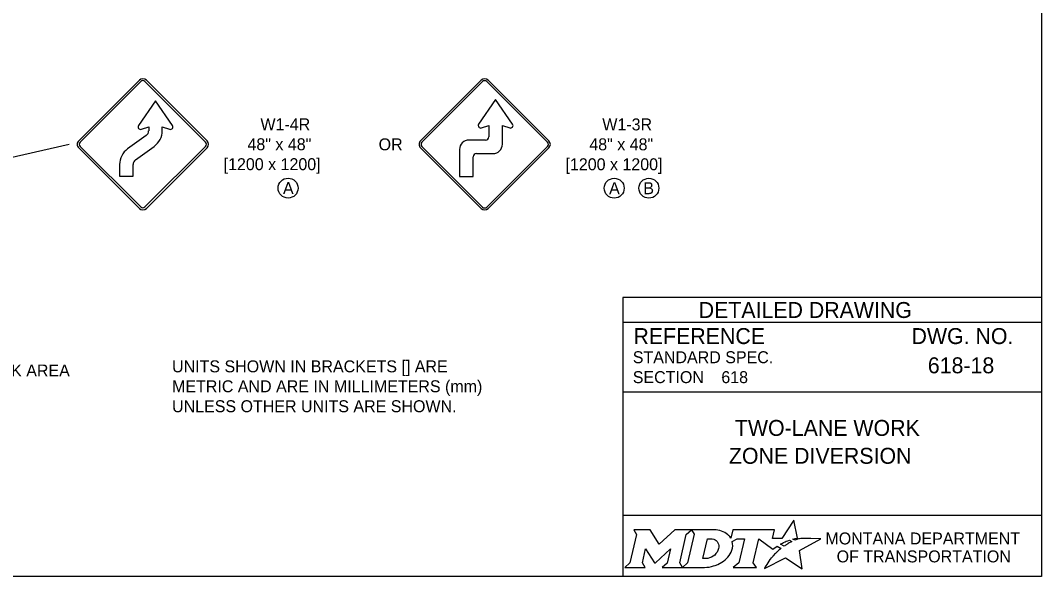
# Model space of a CAD drawing. Extents: x 49991.4 to 50021, y 49987.6 to 50011.4.
# Drawn here: x 50011.63 to 50016.75, y 49987.8 to 49990.59 of the extents above; entities that cross this region are included whole.
import ezdxf

# ---------------------------------------------------------------- set-up
doc = ezdxf.new("R2010")
doc.units = 0
for name, color, linetype in [('Default', 7, 'Continuous'), ('Level 1', 7, 'Continuous'), ('Level 2', 7, 'Continuous'), ('Level 3', 7, 'Continuous'), ('Level 5', 7, 'Continuous')]:
    doc.layers.add(name, color=color, linetype=linetype)

msp = doc.modelspace()

# ---------------------------------------------------------------- linework, layer by layer
at = {"layer": 'Default'}
for points in [[(50015.5126, 49987.9811), (50015.5023, 49987.9867), (50015.5139, 49987.9895), (50015.5255, 49987.9915), (50015.5081, 49988.0816), (50015.4486, 49987.9903), (50015.4013, 49987.9896), (50015.4116, 49988.0337), (50015.2024, 49988.0338), (50015.1923, 49987.9913), (50015.1865, 49987.9996)], [(50014.7056, 49988.0338), (50014.7197, 49988.0104), (50014.6862, 49987.8671), (50014.6605, 49987.8446), (50014.7621, 49987.8446), (50014.7486, 49987.8674), (50014.7648, 49987.9375), (50014.8085, 49987.8685), (50014.8138, 49987.8685), (50014.8889, 49987.938), (50014.8725, 49987.8669), (50014.8478, 49987.8449), (50014.9494, 49987.8449), (50014.9356, 49987.8682), (50014.9688, 49988.0106)], [(50014.9688, 49988.0106), (50014.9941, 49988.0338), (50014.9117, 49988.0338), (50014.8321, 49987.9608), (50014.7876, 49988.0335), (50014.7056, 49988.0338)], [(50015.1077, 49988.0338), (50014.9941, 49988.0338), (50015.0088, 49988.0109), (50014.9749, 49987.8671), (50014.9494, 49987.8449), (50015.06, 49987.8449)], [(50015.1317, 49987.9471), (50015.1305, 49987.939), (50015.1273, 49987.9297), (50015.1231, 49987.9215), (50015.1175, 49987.914), (50015.111, 49987.9071), (50015.1031, 49987.9008), (50015.0948, 49987.8961), (50015.0857, 49987.8922), (50015.0766, 49987.8899), (50015.0674, 49987.889), (50015.0515, 49987.889), (50015.0751, 49987.989), (50015.0911, 49987.989), (50015.0987, 49987.9884), (50015.1063, 49987.9865), (50015.1129, 49987.9835), (50015.119, 49987.9793), (50015.1238, 49987.9743), (50015.1275, 49987.9683), (50015.1302, 49987.9621), (50015.1318, 49987.9547), (50015.1318, 49987.9517), (50015.1317, 49987.9471)], [(50015.1991, 49987.9747), (50015.2237, 49987.9878), (50015.2606, 49987.9878), (50015.232, 49987.8673), (50015.2045, 49987.8446), (50015.3207, 49987.8446), (50015.3037, 49987.8675), (50015.3319, 49987.9877), (50015.4032, 49987.936), (50015.4243, 49987.9511), (50015.444, 49987.9402)], [(50015.3882, 49987.8843), (50015.3729, 49987.8599), (50015.3682, 49987.8524), (50015.3624, 49987.8438), (50015.3601, 49987.8395), (50015.4654, 49987.8926), (50015.5493, 49987.8375), (50015.5362, 49987.9302), (50015.6431, 49987.9886), (50015.5938, 49987.9894), (50015.5637, 49987.9898), (50015.5429, 49987.9901), (50015.5361, 49987.9886), (50015.5312, 49987.9874), (50015.5228, 49987.9851), (50015.5126, 49987.9811)], [(50015.4622, 49987.9535), (50015.4598, 49987.9518), (50015.4415, 49987.9614), (50015.4518, 49987.9671), (50015.4559, 49987.9693), (50015.4645, 49987.9733), (50015.4702, 49987.9759), (50015.4781, 49987.9789), (50015.4854, 49987.9816), (50015.4972, 49987.9742), (50015.4932, 49987.9721), (50015.4886, 49987.9696), (50015.4844, 49987.9674), (50015.4794, 49987.9645), (50015.4775, 49987.9634), (50015.4748, 49987.9618), (50015.4723, 49987.9604), (50015.47, 49987.9588), (50015.4674, 49987.957), (50015.4647, 49987.9552), (50015.4622, 49987.9535)], [(50015.1057, 49987.8522), (50015.1141, 49987.8548), (50015.1271, 49987.8602), (50015.1475, 49987.8712)], [(50015.4021, 49987.9004), (50015.4021, 49987.9004)]]:
    msp.add_lwpolyline(points, dxfattribs=at)
for centre, radius, start, end in [((50015.1308, 49987.9554), 0.0709, 339.5329, 15.8582), ((50015.0868, 49987.9727), 0.1183, 300.9103, 339.1383)]:
    msp.add_arc(centre, radius, start, end, dxfattribs=at)
for centre, major_axis, ratio, start_param, end_param in [((50015.1056, 49987.9864), (0.0834, -0.0037), 0.568097, 0.61298, 1.570796), ((50015.1612, 49987.9937), (0.0361, -0.0295), 0.469099, 1.225588, 1.570796), ((50015.4119, 49987.9106), (-0.0098, -0.0102), 0.016458, 3.141593, 6.279097), ((50015.4329, 49987.9305), (-0.0112, -0.0097), 0.021651, 3.157348, 6.283185), ((50015.0603, 49987.9932), (0, 0.1484), 0.987302, 3.139398, 3.456847), ((50015.3952, 49987.8923), (-0.00694, -0.00806), 0.008222, 0, 3.137361)]:
    msp.add_ellipse(centre, major_axis=major_axis, ratio=ratio, start_param=start_param, end_param=end_param, dxfattribs=at)
at = {"layer": 'Level 1'}
for p, q in [((50011.9223, 49989.9854), (50012.2264, 49990.2894)), ((50011.9294, 49989.9783), (50012.2334, 49990.2824)), ((50012.2546, 49990.2824), (50012.5587, 49989.9783)), ((50012.2617, 49990.2894), (50012.5658, 49989.9854)), ((50013.6363, 49989.985), (50013.9404, 49990.289)), ((50013.6434, 49989.9779), (50013.9474, 49990.282)), ((50013.9687, 49990.282), (50014.2727, 49989.9779)), ((50013.9757, 49990.289), (50014.2798, 49989.985)), ((50012.3071, 49990.1861), (50012.2221, 49990.0624)), ((50012.3923, 49990.0624), (50012.3071, 49990.1861)), ((50014.0128, 49990.193), (50013.9277, 49990.0693)), ((50014.0979, 49990.0693), (50014.0128, 49990.193)), ((50012.2367, 49990.0427), (50012.2732, 49990.0545)), ((50012.2732, 49990.0545), (50012.2732, 49990.0357)), ((50012.3411, 49990.0357), (50012.3411, 49990.0545)), ((50012.3411, 49990.0545), (50012.3776, 49990.0427)), ((50013.9424, 49990.0497), (50013.9788, 49990.0615)), ((50013.9788, 49990.0615), (50013.9788, 49990.005)), ((50014.0468, 49989.9678), (50014.0468, 49990.0615)), ((50014.0468, 49990.0615), (50014.0832, 49990.0497)), ((50012.2611, 49990.012), (50012.1675, 49989.9445)), ((50012.2264, 49989.646), (50011.9223, 49989.95)), ((50012.2334, 49989.653), (50011.9294, 49989.9571)), ((50012.2072, 49989.8893), (50012.3008, 49989.9569)), ((50012.5587, 49989.9571), (50012.2546, 49989.653)), ((50012.5658, 49989.95), (50012.2617, 49989.646)), ((50013.9474, 49989.6526), (50013.6434, 49989.9567)), ((50013.9627, 49989.9888), (50013.8789, 49989.9888)), ((50014.2727, 49989.9567), (50013.9687, 49989.6526)), ((50013.9404, 49989.6456), (50013.6363, 49989.9496)), ((50013.832, 49989.9419), (50013.832, 49989.806)), ((50013.8999, 49989.806), (50013.8999, 49989.9047)), ((50013.9161, 49989.9208), (50013.9999, 49989.9208)), ((50014.2798, 49989.9496), (50013.9757, 49989.6456)), ((50012.1272, 49989.8658), (50012.1272, 49989.8075)), ((50012.1951, 49989.8075), (50012.1951, 49989.8658)), ((50012.1272, 49989.8075), (50012.1951, 49989.8075)), ((50013.832, 49989.806), (50013.8999, 49989.806))]:
    msp.add_line(p, q, dxfattribs=at)
msp.add_lwpolyline([(49999.3835, 49998.9992), (50016.7501, 49998.9992), (50016.7501, 49987.7988), (49999.3835, 49987.7988)], close=True, dxfattribs=at)
for centre, radius, start, end in [((50012.244, 49990.2718), 0.025, 45, 135), ((50012.244, 49990.2718), 0.015, 45, 135), ((50013.958, 49990.2714), 0.025, 45, 135), ((50013.958, 49990.2714), 0.015, 45, 135), ((50012.2327, 49990.0551), 0.0129, 145.4806, 287.9582), ((50012.3815, 49990.0551), 0.0129, 252.0418, 34.5194), ((50013.9384, 49990.062), 0.0129, 145.4806, 287.9582), ((50014.0872, 49990.062), 0.0129, 252.0418, 34.5194), ((50012.244, 49990.0357), 0.0291, 305.7972, 0), ((50012.244, 49990.0357), 0.0971, 305.7972, 0), ((50013.9626, 49990.005), 0.0162, 270, 0), ((50011.9399, 49989.9678), 0.025, 134.9998, 225), ((50011.9399, 49989.9678), 0.015, 134.9998, 225), ((50012.5481, 49989.9678), 0.015, 315, 45), ((50012.5481, 49989.9678), 0.025, 315, 45), ((50013.654, 49989.9673), 0.025, 134.9998, 225), ((50013.654, 49989.9673), 0.015, 134.9998, 225), ((50013.8789, 49989.9419), 0.0469, 90, 180), ((50013.9998, 49989.9678), 0.0469, 270, 0), ((50014.2621, 49989.9673), 0.015, 315, 45), ((50014.2621, 49989.9673), 0.025, 315, 45), ((50012.2242, 49989.8658), 0.0971, 125.7972, 180), ((50013.9161, 49989.9047), 0.0162, 90, 180), ((50012.2242, 49989.8658), 0.0291, 125.7974, 180), ((50012.244, 49989.6637), 0.025, 225.0004, 315), ((50012.244, 49989.6637), 0.015, 225.0004, 315), ((50013.958, 49989.6633), 0.025, 225.0004, 315), ((50013.958, 49989.6633), 0.015, 225.0004, 315)]:
    msp.add_arc(centre, radius, start, end, dxfattribs=at)
at = {"layer": 'Level 2'}
for centre in [(50012.9722, 49989.7478), (50014.6074, 49989.7473), (50014.7812, 49989.7473)]:
    msp.add_circle(centre, 0.05, dxfattribs=at)
at = {"layer": 'Level 3'}
msp.add_line((50010.0904, 49989.5602), (50011.8749, 49989.9678), dxfattribs=at)
at = {"layer": 'Level 5'}
for p, q in [((50016.7501, 49989.1988), (50014.6501, 49989.1988)), ((50014.6501, 49989.1988), (50014.6501, 49987.7988)), ((50016.7501, 49989.0738), (50014.6501, 49989.0738)), ((50016.3862, 49988.8587), (50016.3862, 49988.8587)), ((50015.1444, 49988.7993), (50015.1444, 49988.7993)), ((50016.7501, 49988.7238), (50014.6501, 49988.7238)), ((50015.7001, 49988.4747), (50015.7001, 49988.4747)), ((50016.7501, 49988.1057), (50014.6501, 49988.1057))]:
    msp.add_line(p, q, dxfattribs=at)

# ---------------------------------------------------------------- texts
at = {"layer": 'Default'}
for s, p in [('MONTANA DEPARTMENT', (50015.6663, 49987.96)), ('OF TRANSPORTATION', (50015.7225, 49987.87))]:
    msp.add_text(s, height=0.06, dxfattribs=at).set_placement(p)
at = {"layer": 'Level 2'}
for s, height, p in [('W1-4R', 0.06, (50012.8336, 49990.0378)), ('W1-3R', 0.06, (50014.5476, 49990.0373)), ('48" x 48"', 0.06, (50012.7685, 49989.9378)), ('OR', 0.06, (50013.4261, 49989.9373)), ('48" x 48"', 0.06, (50014.4825, 49989.9373)), ('[1200 x 1200]', 0.06, (50012.649, 49989.8378)), ('[1200 x 1200]', 0.06, (50014.3631, 49989.8373)), ('A', 0.06, (50012.9465, 49989.7178)), ('A', 0.06, (50014.5817, 49989.7173)), ('B', 0.06, (50014.7534, 49989.7173)), ('UNITS SHOWN IN BRACKETS [] ARE ', 0.06, (50012.3904, 49988.8235)), ('618-18', 0.08, (50016.1798, 49988.8187)), ('WORK AREA', 0.06, (50011.3874, 49988.8027)), ('618', 0.06, (50015.1444, 49988.7693)), ('METRIC AND ARE IN MILLIMETERS (mm) ', 0.06, (50012.3904, 49988.7235)), ('UNLESS OTHER UNITS ARE SHOWN.', 0.06, (50012.3904, 49988.6235)), ('TWO-LANE WORK', 0.08, (50015.2123, 49988.5047)), ('ZONE DIVERSION', 0.08, (50015.1824, 49988.3647))]:
    msp.add_text(s, height=height, dxfattribs=at).set_placement(p)
at = {"layer": 'Level 5'}
for s, height, p in [('DETAILED DRAWING', 0.0799, (50015.0311, 49989.0963)), ('REFERENCE', 0.08, (50014.7037, 49988.9654)), ('DWG. NO.', 0.08, (50016.0979, 49988.9654)), ('STANDARD SPEC.', 0.06, (50014.7004, 49988.8694)), ('SECTION', 0.06, (50014.7004, 49988.7694))]:
    msp.add_text(s, height=height, dxfattribs=at).set_placement(p)

doc.saveas('drawing.dxf')
